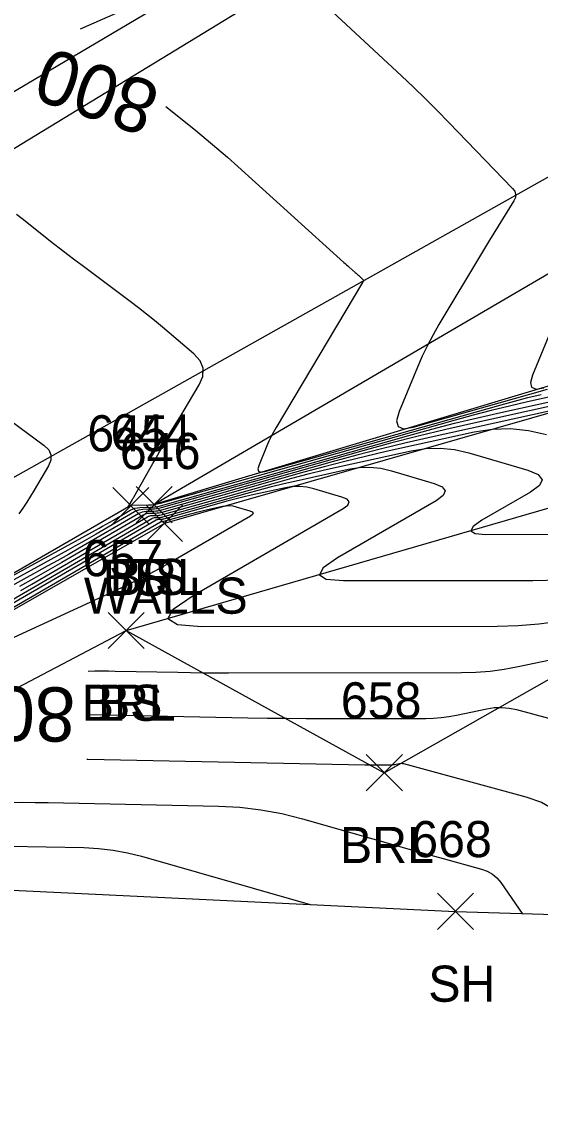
# Model space of a CAD drawing. Extents: x 1650836 to 1652450, y 332578 to 333908.
# Drawn here: x 1652108.4 to 1652137.1, y 332628.3 to 332688.4 of the extents above; entities that cross this region are included whole.
import ezdxf

# ---------------------------------------------------------------- set-up
doc = ezdxf.new("R2010")
doc.units = 0
for name, color, linetype in [('L_A', 7, 'Continuous'), ('L_I', 7, 'Continuous'), ('L_TIC', 7, 'Continuous'), ('LABL', 7, 'Continuous'), ('LELB', 7, 'Continuous'), ('LSOGCMA', 7, 'Continuous'), ('LSOGCMA_T', 7, 'Continuous'), ('LSOGCMI', 7, 'Continuous'), ('LSOGP', 7, 'Continuous'), ('LWS', 7, 'Continuous'), ('PEU', 7, 'Continuous')]:
    doc.layers.add(name, color=color, linetype=linetype)

msp = doc.modelspace()

# ---------------------------------------------------------------- linework, layer by layer
at = {"layer": 'L_TIC'}
for points in [[(1652113.452, 332660.6), (1652115.452, 332662.6)], [(1652115.452, 332660.6), (1652113.452, 332662.6)], [(1652114.739, 332660.653), (1652116.739, 332662.653)], [(1652116.739, 332660.653), (1652114.739, 332662.653)], [(1652114.739, 332660.653), (1652116.739, 332662.653)], [(1652116.739, 332660.653), (1652114.739, 332662.653)], [(1652115.306, 332659.618), (1652117.306, 332661.618)], [(1652117.306, 332659.618), (1652115.306, 332661.618)], [(1652113.189, 332653.693), (1652115.189, 332655.693)], [(1652115.189, 332653.693), (1652113.189, 332655.693)], [(1652113.189, 332653.693), (1652115.189, 332655.693)], [(1652115.189, 332653.693), (1652113.189, 332655.693)], [(1652127.474, 332645.824), (1652129.474, 332647.824)], [(1652129.474, 332645.824), (1652127.474, 332647.824)], [(1652131.417, 332638.149), (1652133.417, 332640.149)], [(1652133.417, 332638.149), (1652131.417, 332640.149)]]:
    msp.add_lwpolyline(points, dxfattribs=at)
at = {"layer": 'LABL'}
for points in [[(1652188.25, 332681.448), (1652183.53, 332688.882), (1652149.671, 332675.169), (1652142.015, 332669.547), (1652115.739, 332661.653)], [(1652114.189, 332654.693), (1652128.474, 332646.824), (1652153.961, 332661.301), (1652188.041, 332667.268)]]:
    msp.add_lwpolyline(points, dxfattribs=at)
at = {"layer": 'LELB'}
for points in [[(1652054.928, 332654.589), (1652089.949, 332673.854), (1652132.975, 332699.313), (1652151.656, 332710.875), (1652169.833, 332727.743)], [(1652223.641, 332705.756), (1652202.971, 332707.089), (1652180.593, 332697.892), (1652146.001, 332679.364), (1652115.739, 332661.653)], [(1652101.093, 332647.816), (1652114.189, 332654.693), (1652146.823, 332664.15), (1652153.664, 332667.075), (1652184.838, 332674.254)], [(1652114.452, 332661.6), (1652102.311, 332654.602), (1652064.084, 332631.537)]]:
    msp.add_lwpolyline(points, dxfattribs=at)
at = {"layer": 'LSOGCMA'}
for points in [[(1652116.388, 332683.685), (1652118.022, 332682.372), (1652118.622, 332681.883), (1652119.214, 332681.385), (1652119.799, 332680.878), (1652120.376, 332680.362), (1652126.234, 332675.052), (1652126.306, 332674.987), (1652126.378, 332674.923), (1652126.45, 332674.86), (1652126.523, 332674.797), (1652126.858, 332674.506), (1652126.908, 332674.462), (1652126.958, 332674.417), (1652127.007, 332674.372), (1652127.055, 332674.326), (1652127.325, 332674.065), (1652127.332, 332674.056), (1652127.335, 332674.046), (1652127.334, 332674.036), (1652127.329, 332674.025), (1652127.303, 332673.982), (1652127.289, 332673.96), (1652127.276, 332673.938), (1652122.483, 332665.917), (1652122.342, 332665.671), (1652122.21, 332665.42), (1652122.088, 332665.165), (1652121.975, 332664.905), (1652121.542, 332663.856), (1652121.481, 332663.636), (1652121.516, 332663.501), (1652121.646, 332663.451), (1652121.871, 332663.486), (1652134.941, 332667.184), (1652135.674, 332667.386), (1652136.409, 332667.577), (1652137.148, 332667.756)], [(1652148.647, 332638.656), (1652142.698, 332647.266), (1652142.159, 332647.922), (1652141.534, 332648.455), (1652140.822, 332648.866), (1652140.024, 332649.154), (1652135.801, 332650.295), (1652135.388, 332650.381), (1652134.973, 332650.417), (1652134.558, 332650.403), (1652134.14, 332650.34), (1652132.469, 332649.984), (1652132.049, 332649.907), (1652131.628, 332649.851), (1652131.204, 332649.817), (1652130.778, 332649.806), (1652125.212, 332649.802), (1652124.142, 332649.804), (1652123.072, 332649.812), (1652122.002, 332649.825), (1652120.932, 332649.845), (1652112.944, 332650.009), (1652112.161, 332650.022), (1652112.05, 332650.022)]]:
    msp.add_lwpolyline(points, dxfattribs=at)
at = {"layer": 'LSOGCMI'}
for points in [[(1652111.658, 332687.97), (1652119.696, 332691.521)], [(1652123.552, 332690.835), (1652129.42, 332685.378), (1652130.088, 332684.747), (1652130.748, 332684.108), (1652131.399, 332683.46), (1652132.042, 332682.803), (1652135.571, 332679.147), (1652135.688, 332678.988), (1652135.74, 332678.821), (1652135.725, 332678.648), (1652135.644, 332678.468), (1652134.291, 332676.279), (1652134.18, 332676.098), (1652134.069, 332675.917), (1652133.959, 332675.735), (1652133.849, 332675.552), (1652131.497, 332671.616), (1652131.168, 332671.041), (1652130.86, 332670.456), (1652130.574, 332669.859), (1652130.31, 332669.252), (1652129.298, 332666.8), (1652129.156, 332666.287), (1652129.237, 332665.971), (1652129.541, 332665.854), (1652130.068, 332665.936), (1652137.494, 332668.037)], [(1652141.766, 332668.521), (1652136.4, 332667.34), (1652135.392, 332667.11), (1652134.387, 332666.865), (1652133.385, 332666.606), (1652132.388, 332666.332), (1652116.067, 332661.713), (1652115.91, 332661.674), (1652115.752, 332661.645), (1652115.591, 332661.627), (1652115.43, 332661.618), (1652114.464, 332661.598), (1652114.46, 332661.598), (1652114.456, 332661.597), (1652114.452, 332661.595), (1652114.448, 332661.593), (1652114.426, 332661.581), (1652114.419, 332661.577), (1652114.293, 332661.508), (1652114.281, 332661.502), (1652114.275, 332661.502), (1652114.276, 332661.508), (1652114.283, 332661.519), (1652114.334, 332661.588), (1652114.339, 332661.596), (1652114.345, 332661.603), (1652114.349, 332661.611), (1652114.354, 332661.619), (1652114.523, 332661.909), (1652114.547, 332661.949), (1652114.57, 332661.99), (1652114.594, 332662.03), (1652114.617, 332662.071), (1652115.668, 332663.924), (1652115.852, 332664.246), (1652116.037, 332664.567), (1652116.224, 332664.887), (1652116.412, 332665.206), (1652118.232, 332668.276), (1652118.432, 332668.752), (1652118.451, 332669.197), (1652118.288, 332669.612), (1652117.943, 332669.996), (1652116.2, 332671.472), (1652115.762, 332671.838), (1652115.318, 332672.196), (1652114.868, 332672.548), (1652114.414, 332672.893), (1652111.751, 332674.878), (1652111.353, 332675.177), (1652110.957, 332675.479), (1652110.563, 332675.784), (1652110.171, 332676.091), (1652108.436, 332677.463), (1652108.129, 332677.701)], [(1652139.18, 332674.892), (1652136.674, 332668.825), (1652136.557, 332668.403), (1652136.624, 332668.144), (1652136.874, 332668.047), (1652137.307, 332668.114)], [(1652105.933, 332656.645), (1652112.693, 332660.356), (1652112.892, 332660.466), (1652113.09, 332660.577), (1652113.287, 332660.69), (1652113.484, 332660.803), (1652114.414, 332661.343), (1652114.541, 332661.407), (1652114.673, 332661.453), (1652114.81, 332661.482), (1652114.951, 332661.494), (1652115.528, 332661.506), (1652115.672, 332661.514), (1652115.814, 332661.53), (1652115.955, 332661.556), (1652116.094, 332661.591), (1652129.835, 332665.479), (1652131.097, 332665.826), (1652132.364, 332666.154), (1652133.635, 332666.464), (1652134.911, 332666.755), (1652142.212, 332668.362)], [(1652142.657, 332668.202), (1652133.423, 332666.17), (1652131.879, 332665.818), (1652130.341, 332665.443), (1652128.809, 332665.046), (1652127.282, 332664.626), (1652116.121, 332661.468), (1652115.999, 332661.438), (1652115.876, 332661.415), (1652115.752, 332661.401), (1652115.626, 332661.394), (1652115.122, 332661.384), (1652114.998, 332661.373), (1652114.879, 332661.348), (1652114.763, 332661.307), (1652114.652, 332661.252), (1652112.534, 332660.021), (1652112.144, 332659.796), (1652111.753, 332659.574), (1652111.361, 332659.353), (1652110.967, 332659.136), (1652103.297, 332654.925)], [(1652105.452, 332668.032), (1652109.658, 332664.932), (1652109.908, 332664.688), (1652110.031, 332664.417), (1652110.025, 332664.12), (1652109.893, 332663.797), (1652109.107, 332662.45), (1652108.906, 332662.117), (1652108.697, 332661.788), (1652108.479, 332661.466), (1652108.253, 332661.149)], [(1652137.767, 332666.868), (1652131.066, 332665.393), (1652129.688, 332665.079), (1652128.315, 332664.745), (1652126.947, 332664.39), (1652125.584, 332664.016), (1652116.148, 332661.345), (1652116.043, 332661.319), (1652115.938, 332661.3), (1652115.832, 332661.288), (1652115.724, 332661.282), (1652115.293, 332661.273), (1652115.187, 332661.264), (1652115.085, 332661.243), (1652114.986, 332661.208), (1652114.891, 332661.16), (1652111.585, 332659.239), (1652111.002, 332658.903), (1652110.417, 332658.57), (1652109.829, 332658.241), (1652109.24, 332657.915), (1652104.512, 332655.319)], [(1652137.449, 332665.516), (1652136.453, 332665.745), (1652135.452, 332665.845), (1652134.447, 332665.816), (1652133.437, 332665.658), (1652128.575, 332664.588), (1652127.43, 332664.326), (1652126.289, 332664.049), (1652125.151, 332663.754), (1652124.019, 332663.442), (1652116.174, 332661.223), (1652116.088, 332661.201), (1652116, 332661.185), (1652115.912, 332661.175), (1652115.823, 332661.17), (1652115.464, 332661.163), (1652115.376, 332661.155), (1652115.291, 332661.137), (1652115.209, 332661.108), (1652115.13, 332661.069), (1652110.635, 332658.457), (1652109.859, 332658.01), (1652109.08, 332657.566), (1652108.298, 332657.128)], [(1652108.359, 332656.907), (1652108.971, 332657.26), (1652115.369, 332660.977), (1652115.432, 332661.009), (1652115.497, 332661.032), (1652115.565, 332661.046), (1652115.635, 332661.052), (1652115.921, 332661.058), (1652115.992, 332661.062), (1652116.062, 332661.07), (1652116.132, 332661.083), (1652116.201, 332661.1), (1652122.453, 332662.869), (1652123.356, 332663.117), (1652124.262, 332663.352), (1652125.172, 332663.574), (1652126.085, 332663.782), (1652129.959, 332664.635), (1652130.764, 332664.761), (1652131.565, 332664.784), (1652132.363, 332664.705), (1652133.157, 332664.522), (1652136.421, 332663.558), (1652136.989, 332663.317), (1652137.202, 332663.034), (1652137.061, 332662.709), (1652136.566, 332662.341), (1652133.878, 332660.786), (1652133.387, 332660.446), (1652133.258, 332660.204), (1652133.491, 332660.058), (1652134.086, 332660.01), (1652139.988, 332660.015)], [(1652107.274, 332656.044), (1652115.608, 332660.886), (1652115.655, 332660.909), (1652115.703, 332660.927), (1652115.754, 332660.937), (1652115.806, 332660.942), (1652116.019, 332660.946), (1652116.072, 332660.949), (1652116.125, 332660.955), (1652116.177, 332660.964), (1652116.228, 332660.977), (1652120.887, 332662.296), (1652121.56, 332662.481), (1652122.236, 332662.656), (1652122.913, 332662.821), (1652123.594, 332662.976), (1652126.481, 332663.612), (1652127.081, 332663.706), (1652127.679, 332663.723), (1652128.273, 332663.664), (1652128.865, 332663.528), (1652131.226, 332662.83), (1652131.676, 332662.639), (1652131.846, 332662.415), (1652131.734, 332662.157), (1652131.341, 332661.865), (1652125.885, 332658.71), (1652125.091, 332658.16), (1652124.882, 332657.767), (1652125.259, 332657.532), (1652126.222, 332657.454), (1652136.693, 332657.462), (1652138.214, 332657.502)], [(1652138.169, 332655.182), (1652137.026, 332655.032), (1652135.877, 332654.941), (1652134.722, 332654.91), (1652118.358, 332654.898), (1652117.028, 332655.005), (1652116.506, 332655.33), (1652116.794, 332655.873), (1652117.892, 332656.633), (1652126.203, 332661.439), (1652126.461, 332661.631), (1652126.534, 332661.801), (1652126.423, 332661.949), (1652126.127, 332662.074), (1652124.572, 332662.533), (1652124.183, 332662.623), (1652123.792, 332662.662), (1652123.399, 332662.65), (1652123.004, 332662.589), (1652121.103, 332662.17), (1652120.655, 332662.068), (1652120.209, 332661.959), (1652119.764, 332661.844), (1652119.322, 332661.722), (1652116.255, 332660.855), (1652116.221, 332660.846), (1652116.187, 332660.84), (1652116.152, 332660.836), (1652116.117, 332660.834), (1652115.977, 332660.831), (1652115.943, 332660.828), (1652115.909, 332660.821), (1652115.877, 332660.81), (1652115.847, 332660.794), (1652105.578, 332654.829)], [(1652103.882, 332653.613), (1652116.085, 332660.703), (1652116.1, 332660.71), (1652116.116, 332660.716), (1652116.132, 332660.719), (1652116.148, 332660.721), (1652116.216, 332660.722), (1652116.232, 332660.723), (1652116.249, 332660.725), (1652116.265, 332660.728), (1652116.282, 332660.732), (1652117.756, 332661.149), (1652117.969, 332661.208), (1652118.182, 332661.263), (1652118.397, 332661.315), (1652118.612, 332661.364), (1652119.526, 332661.565), (1652119.716, 332661.595), (1652119.905, 332661.601), (1652120.093, 332661.582), (1652120.28, 332661.539), (1652121.027, 332661.318), (1652121.17, 332661.258), (1652121.223, 332661.187), (1652121.188, 332661.105), (1652121.064, 332661.013), (1652116.784, 332658.538), (1652116.01, 332658.102), (1652115.226, 332657.685), (1652114.432, 332657.286), (1652113.629, 332656.905), (1652107.258, 332653.977)], [(1652112.086, 332652.449), (1652112.09, 332652.449), (1652112.466, 332652.454), (1652112.841, 332652.456), (1652113.217, 332652.453), (1652113.592, 332652.448), (1652117.046, 332652.376), (1652117.746, 332652.364), (1652118.447, 332652.355), (1652119.148, 332652.35), (1652119.849, 332652.348), (1652132.75, 332652.358), (1652133.541, 332652.379), (1652134.327, 332652.441), (1652135.109, 332652.544), (1652135.887, 332652.689), (1652139.336, 332653.422)], [(1652112.014, 332647.576), (1652112.065, 332647.576), (1652127.387, 332647.26), (1652127.542, 332647.257), (1652127.696, 332647.255), (1652127.85, 332647.254), (1652128.004, 332647.254), (1652128.806, 332647.254), (1652128.868, 332647.256), (1652128.929, 332647.261), (1652128.99, 332647.269), (1652129.05, 332647.28), (1652129.291, 332647.331), (1652129.351, 332647.34), (1652129.411, 332647.342), (1652129.471, 332647.337), (1652129.53, 332647.325), (1652136.308, 332645.495), (1652137.165, 332645.185), (1652137.929, 332644.744), (1652138.6, 332644.171), (1652139.179, 332643.467), (1652142.372, 332638.847)], [(1652107.737, 332645.182), (1652108.45, 332645.184), (1652109.163, 332645.18), (1652109.876, 332645.169), (1652119.296, 332644.975), (1652120.476, 332644.913), (1652121.644, 332644.775), (1652122.801, 332644.563), (1652123.947, 332644.275), (1652129.857, 332642.588), (1652130.322, 332642.456), (1652130.788, 332642.326), (1652131.254, 332642.197), (1652131.721, 332642.07), (1652133.855, 332641.494), (1652134.172, 332641.379), (1652134.454, 332641.216), (1652134.702, 332641.005), (1652134.916, 332640.744), (1652136.096, 332639.037)], [(1652107.686, 332642.762), (1652111.857, 332642.676), (1652112.665, 332642.634), (1652113.465, 332642.54), (1652114.258, 332642.394), (1652115.043, 332642.197), (1652124.367, 332639.535)]]:
    msp.add_lwpolyline(points, dxfattribs=at)
at = {"layer": 'LSOGP'}
msp.add_lwpolyline([(1651984.523, 332752.343), (1651991.57, 332730.62), (1651991.353, 332729.831), (1651992.861, 332722.96), (1651995.915, 332712.612), (1651995.92, 332711.781), (1652013.872, 332713.448), (1652022.272, 332696.192), (1652039.797, 332682.479), (1652040.117, 332681.915), (1652040.875, 332679.562), (1652040.399, 332672.943), (1652048.756, 332662.461), (1652054.928, 332654.589), (1652056.971, 332651.823), (1652062.738, 332635.184), (1652064.084, 332631.537), (1652064.185, 332630.255), (1652077.816, 332635.004), (1652091.228, 332633.028), (1652105.571, 332640.437), (1652132.417, 332639.149), (1652165.837, 332638.134)], dxfattribs=at)
at = {"layer": 'LWS'}
msp.add_lwpolyline([(1652208.992, 332628.311), (1652198.531, 332678.869), (1652152.626, 332670.878), (1652142.717, 332668.181), (1652116.306, 332660.618), (1652103.236, 332653.15), (1652064.185, 332630.255)], dxfattribs=at)
at = {"layer": 'PEU'}
for points in [[(1652056.971, 332651.823), (1652091.078, 332671.061), (1652133.854, 332697.145), (1652158.219, 332712.634)], [(1652178.884, 332701.373), (1652143.147, 332682.921), (1652100.303, 332658.865), (1652062.738, 332635.184)]]:
    msp.add_lwpolyline(points, dxfattribs=at)

# ---------------------------------------------------------------- texts
at = {"layer": 'L_A'}
for s, p in [('BS', (1652112.893, 332656.6)), ('BRL', (1652113.282, 332656.653)), ('TS', (1652114.149, 332656.653)), ('WALLS', (1652111.85, 332655.618)), ('BRL', (1652111.732, 332649.693)), ('BS', (1652112.63, 332649.693)), ('BRL', (1652126.018, 332641.824)), ('SH', (1652130.906, 332634.149))]:
    msp.add_text(s, height=2, dxfattribs=at).set_placement(p)
at = {"layer": 'L_I'}
for s, p in [('645', (1652112.042, 332664.6)), ('644', (1652113.33, 332664.653)), ('644', (1652113.33, 332664.653)), ('646', (1652113.842, 332663.618)), ('657', (1652111.78, 332657.693)), ('657', (1652111.78, 332657.693)), ('658', (1652126.065, 332649.824)), ('668', (1652129.961, 332642.149))]:
    msp.add_text(s, height=2, dxfattribs=at).set_placement(p)
at = {"layer": 'LSOGCMA_T'}
for s, rotation, p in [('800', 161.24664, (1652116.207, 332684.842)), ('805', 179.15833, (1652111.399, 332651.528))]:
    msp.add_text(s, height=3, rotation=rotation, dxfattribs=at).set_placement(p)

doc.saveas('drawing.dxf')
